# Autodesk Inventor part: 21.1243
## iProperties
Created: 2006-02
Part Number: 21.1243
Material: Steel, Mild
Description: M6 x 30 SHCS
Document SubType Name: Modeling
Standard: DIN 7984
Designer: Andy Moles
Standards Organization: DIN
Language: en-US
Size Designation: M6 x 30
Categories: <MemberInstance><Categories><Category DisplayName="Fasteners" InternalName="e4da775c-781d-43d5-af7c-5136215cf5a6" Mnemonic="FSTN"><Category DisplayName="Bolts"
Density: 1 g/cm^3
Vendor: S
Author: Andy Moles
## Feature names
1. Body [Revolution]
2. Slot [Extrusion]
3. Fillet1
4. Chamfer1
